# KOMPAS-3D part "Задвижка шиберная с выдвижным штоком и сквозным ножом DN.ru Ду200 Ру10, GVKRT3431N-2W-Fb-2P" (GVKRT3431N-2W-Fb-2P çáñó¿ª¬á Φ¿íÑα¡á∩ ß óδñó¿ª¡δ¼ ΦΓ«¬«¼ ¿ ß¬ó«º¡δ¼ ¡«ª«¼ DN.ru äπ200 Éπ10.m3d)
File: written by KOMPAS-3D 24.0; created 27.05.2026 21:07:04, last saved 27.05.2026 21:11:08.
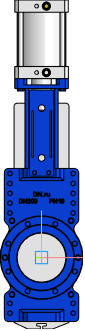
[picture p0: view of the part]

Document properties: Автор: DN.ru; Полное имя файла: C:\Работа\ГОТОВЫЕ ИСХОДНИКИ\GVKRT3431N-2W-Fb-2P Задвижка шиберная со сквозным ножом DN.ru Ду100-250 Ру16\DN200\GVKRT3431N-2W-Fb-2P Задвижка шиберная с выдвижным штоком и сквозным ножом DN.ru Ду200 Ру10.m3d

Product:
- Part/product: Задвижка шиберная с выдвижным штоком и сквозным ножом DN.ru Ду200 Ру10  | designation GVKRT3431N-2W-Fb-2P
    Масса: 50
    Раздел спецификации: Прочие изделия
    Примечание: D040-08532

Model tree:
1. Операция без истории:1

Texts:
  GVKRT3431N-2W-Fb-2P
